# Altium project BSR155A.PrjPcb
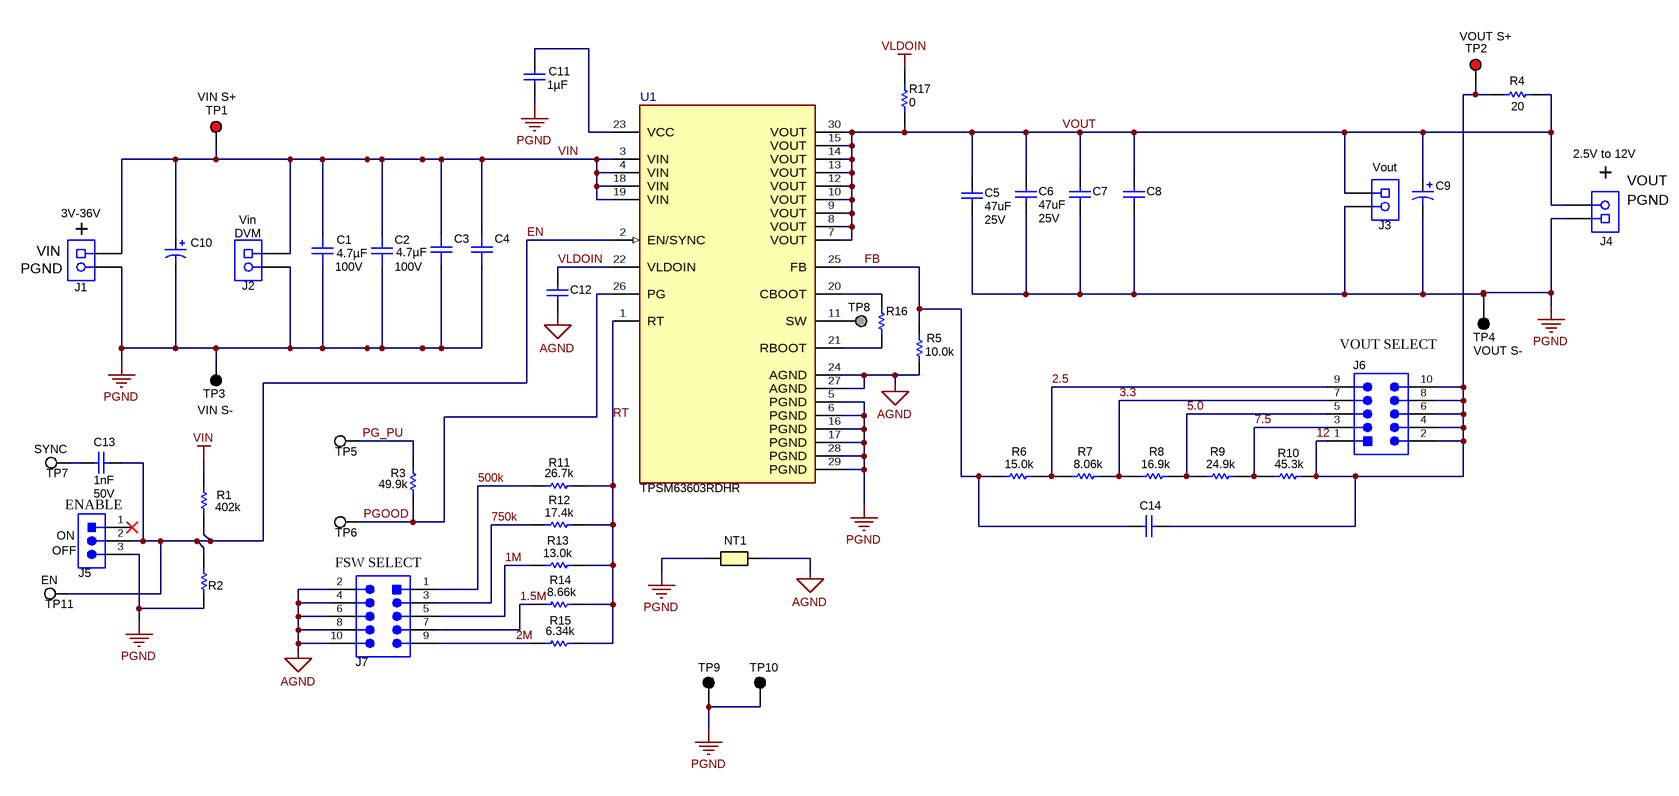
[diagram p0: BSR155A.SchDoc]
CopyrightYear: 2020; EVM_Orderable: TPSM63603EVM; PCB_Layout: Jason Arrigo; PCB_Rev: A; PRJ_Customer: Public Release; PRJ_Engineer: Jason Arrigo; PRJ_Number: BSR155; PRJ_Title: TPSM63603EVM; SCH_Rev: A; TechSupport: http://www.ti.com/support; TID: N/A
1 sheet, 51 parts. Net scope: global (net labels, ports and power ports of the same name join across sheets).
Board files: BSR155A.PcbDoc, BSR155A_ASCII.PcbDoc

## Sheet BSR155A.SchDoc: TPSM63603EVM schematic
size 431 x 279 mm; REV: E1; Date: Not shown in title block; ApprovedBy: Not shown in title block; CheckedBy: Not shown in title block; Author: Not shown in title block; CompanyName: Not shown in title block; DrawnBy: Jason Arrigo; Engineer: Not shown in title block; Organization: Not shown in title block; Address1: Not shown in title block; Address2: Not shown in title block; Address3: Not shown in title block; Address4: Not shown in title block; DocumentNumber: 1; Revision: Use project parameter SCH_Rev; SheetNumber: 1; SheetTotal: 2; PageSetup: Record=PageOptions¦CenterHorizontal=True¦CenterVertical=True¦PrintScale=1.00¦XCorrection=1.00¦YCorrection=1.00¦PrintKind=0¦BorderSize=5000000¦LeftOffset=0¦BottomOffset=0¦Orientation=2¦PaperLength=1000¦PaperWidth=1000¦Scale=100¦PaperSource=15¦PrintQuality=600¦MediaType=1¦DitherType=10¦PaperKind=Letter¦PrintScaleMode=1

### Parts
C1  value 4.7µF  VDC_V: 100V  [FP-GRM31CC72A475KE11L_1206-MFG]  (hidden comment: GRM31CC72A475KE11L)
C2  Cap_F: 4.7µF  VDC_V: 100V  [FP-GRM31CC72A475KE11L_1206-MFG]  (hidden comment: GRM31CC72A475KE11L)
C3  GRM31CC72A475KE11L  [FP-GRM31CC72A475KE11L_1206-MFG]  (value not drawn)
C4  GRM31CC72A475KE11L  [FP-GRM31CC72A475KE11L_1206-MFG]  (value not drawn)
C5  ValueDisplayed: 47uF  VDC_V: 25V  [1206_190L]  (hidden comment: C3216X5R1E476M160AC)
C6  ValueDisplayed: 47uF  VDC_V: 25V  [1206_190L]  (hidden comment: C3216X5R1E476M160AC)
C7  C3216X5R1E476M160AC  [1206_190L]  (value not drawn)
C8  C3216X5R1E476M160AC  [1206_190L]  (value not drawn)
C9  T520Y337M010ATE035  [7343-40]  (value not drawn)
C10  EEEFT1H470AP  [Panasonic_D]  (value not drawn)
C11  Cap_F: 1µF  [0402S]  (hidden comment: EMK105BJ105KVHF)
C12  GRM155R61E105KA12D  [0402S]  (value not drawn)
C13  Cap_F: 1nF  VDC_V: 50V  [0603]  (hidden comment: C0603C102J5RACTU)
C14  GRM188R71C472KA01D  [0603L]  (value not drawn)
J1  OSTTA024163  [On-Shore_OSTTA024163]  (value not drawn)
J2  310-43-102-41-001000  [Mill-max_310-43-102-41-001000]  (value not drawn)
J3  310-43-102-41-001000  [Mill-max_310-43-102-41-001000]  (value not drawn)
J4  OSTTA024163  [On-Shore_OSTTA024163]  (value not drawn)
J5  PEC03SAAN  [CONN_PEC03SAAN]  (value not drawn)
J6  PEC05DAAN  [CONN_PEC05DAAN]  (value not drawn)
J7  PEC05DAAN  [CONN_PEC05DAAN]  (value not drawn)
NT1  Net-Tie  [Net-Tie_10mil]  (value not drawn)  (net tie, no BOM)
R1  ValueDisplayed: 402k  [0603]  (hidden comment: CRCW0603402KFKEA)
R2  CRCW0603133KFKEA  [0603]  (value not drawn)
R3  ValueDisplayed: 49.9k  [0603]  (hidden comment: CRCW060349K9FKEA)
R4  ValueDisplayed: 20  [0603]  (hidden comment: CRCW060320R0JNEA)
R5  ValueDisplayed: 10.0k  [0603]  (hidden comment: CRCW060310K0FKEA)
R6  ValueDisplayed: 15.0k  [0603]  (hidden comment: CRCW060315K0FKEA)
R7  ValueDisplayed: 8.06k  [0603]  (hidden comment: CRCW06038K06FKEA)
R8  ValueDisplayed: 16.9k  [0603]  (hidden comment: CRCW060316K9FKEA)
R9  ValueDisplayed: 24.9k  [0603]  (hidden comment: CRCW060324K9FKEA)
R10  ValueDisplayed: 45.3k  [0603]  (hidden comment: CRCW060345K3FKEA)
R11  ValueDisplayed: 26.7k  [0603]  (hidden comment: CRCW060326K7FKEA)
R12  ValueDisplayed: 17.4k  [0603]  (hidden comment: CRCW060317K4FKEA)
R13  ValueDisplayed: 13.0k  [0603]  (hidden comment: CRCW060313K0FKEA)
R14  ValueDisplayed: 8.66k  [0603]  (hidden comment: CRCW06038K66FKEA)
R15  ValueDisplayed: 6.34k  [0603]  (hidden comment: CRCW06036K34FKEA)
R16  CRCW040210R0JNED  [0402S]  (value not drawn)
R17  ValueDisplayed: 0  [0603]  (hidden comment: RMCF0603ZT0R00)
TP1  5010  [Keystone5010]  (value not drawn)
TP2  5010  [Keystone5010]  (value not drawn)
TP3  5011  [Keystone5011]  (value not drawn)
TP4  5011  [Keystone5011]  (value not drawn)
TP5  5012  [Keystone5012]  (value not drawn)
TP6  5012  [Keystone5012]  (value not drawn)
TP7  5012  [Keystone5012]  (value not drawn)
TP8  TESTPOINT  [TP_25MIL-SMT]  (value not drawn)  (no BOM)
TP9  5011  [Keystone5011]  (value not drawn)
TP10  5011  [Keystone5011]  (value not drawn)
TP11  5012  [Keystone5012]  (value not drawn)
U1  TPSM63603RDHR  [RDH0030A-MFG]

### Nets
AGND: C12.2 J7.2 J7.4 J7.6 J7.8 J7.10 NT1.1 R5.1 U1.24(AGND) U1.27(AGND)
PGND: C1.1 C2.1 C3.1 C4.1 C5.1 C6.1 C7.1 C8.1 C9.2(-) C10.2(-) C11.2 J1.2 J2.2 J3.2 J4.1 J5.3 NT1.2 R2.1 TP3.1 TP4.1 TP9.1 TP10.1 U1.5(PGND) U1.6(PGND) U1.16(PGND) U1.17(PGND) U1.28(PGND) U1.29(PGND)
VIN: C1.2 C2.2 C3.2 C4.2 C10.1(+) J1.1 J2.1 R1.2 TP1.1 U1.3(VIN) U1.4(VIN) U1.18(VIN) U1.19(VIN)
VLDOIN: C12.1 R17.2 U1.22(VLDOIN)
1.5M: J7.7 R14.1
1M: J7.5 R13.1
2.5: J6.9 R6.2 R7.1
2M: J7.9 R15.1
3.3: J6.7 R7.2 R8.1
5.0: J6.5 R8.2 R9.1
7.5: J6.3 R9.2 R10.1
12: C14.2 J6.1 J6.2 J6.4 J6.6 J6.8 J6.10 R4.2 R10.2 TP2.1
500k: J7.1 R11.1
750k: J7.3 R12.1
EN: C13.2 J5.2 R1.1 R2.2 TP11.1 U1.2(EN/SYNC)
FB: C14.1 R5.2 R6.1 U1.25(FB)
PG_PU: R3.1 TP5.1
PGOOD: R3.2 TP6.1 U1.26(PG)
RT: R11.2 R12.2 R13.2 R14.2 R15.2 U1.1(RT)
VOUT: C5.2 C6.2 C7.2 C8.2 C9.1(+) J3.1 J4.2 R4.1 R17.1 U1.7(VOUT) U1.8(VOUT) U1.9(VOUT) U1.10(VOUT) U1.12(VOUT) U1.13(VOUT) U1.14(VOUT) U1.15(VOUT) U1.30(VOUT)
NetC11_1: C11.1 U1.23(VCC)
NetC13_1: C13.1 TP7.1
NetR16_1: R16.1 U1.21(RBOOT)
NetR16_2: R16.2 U1.20(CBOOT)
NetTP8_1: TP8.1 U1.11(SW)

Not connected (* = marked no-connect by the designer): J5 1*

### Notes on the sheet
- (near TP2) VOUT S+
- (near TP1) VIN S+
- (near J1) 3V-36V
- Vout
- (near J4) +
- 2.5V to 12V
- (near J4) PGND
- (near J4) VOUT
- (near J1) PGND
- (near J1) VIN
- (near J1) +
- (near J2) Vin
- (near J2) DVM
- (near TP3) VIN S-
- (near J6) VOUT SELECT
- (near TP4) VOUT S-
- (near TP7) SYNC
- (near J5) ENABLE
- ON
- (near TP11) EN
- OFF
- (near J7) FSW SELECT

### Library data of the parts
C1-C4 = CMP-0089881-1: 4.7µF ±10% 100V Ceramic Capacitor X7S 1206 (3216 Metric); Manufacturer: Murata; ValueDisplayed: 4.7uF; TempCo: 22%; SizeZ_mm: 1.9mm; AEC Qualified: No
C5 C6 = CMP-0008656-2: CAP, CERM, 47 uF, 25 V, +/- 20%, X5R, 1206_190; Manufacturer: TDK; Polarized: N; CompType: Capacitor; Value: 47uF; U/M: EA; Cap_F: 47µF; Value1: Unknown; TaMin_C: -55°C; TaMax_C: 85°C; Cap_Case: 1206; SizeArea_mm2: 5.12; SizeAreaWB_mm2: 10.92; SizeX_mm: 3.2; SizeY_mm: 1.6; SizeZ_mm: 1.9; AEC Category: Q200
C7 C8 = CMP-0008656-2: CAP, CERM, 47 uF, 25 V, +/- 20%, X5R, 1206_190; Manufacturer: TDK; Polarized: N; CompType: Capacitor; Value: 47uF; U/M: EA; Cap_F: 47µF; Value1: Unknown; VDC_V: 25V; TaMin_C: -55°C; TaMax_C: 85°C; Cap_Case: 1206; SizeArea_mm2: 5.12; SizeAreaWB_mm2: 10.92; SizeX_mm: 3.2; SizeY_mm: 1.6; SizeZ_mm: 1.9; AEC Category: Q200
C9 = CMP-0064986-2: CAP, Tantalum Polymer, 330 uF, 10 V,+/- 20%, 0.035 ohm, 7343-40 SMD; Manufacturer: Kemet; TaMin_C: -55°C; ESR_ohm: 0.035; Polarized: Y; SizeAreaWB_mm2: 58.59; Value: 330uF; TaMax_C: 105°C; SizeZ_mm: 4; SizeX_mm: 7.3; SizeY_mm: 4.3; Value2: 10V; SizeArea_mm2: 31.39; CompType: Capacitor; AEC Qualified: N; Cap_F: 330µF; AEC Category: Q200
C10 = CMP-0011204-2: CAP, AL, 47 uF, 50 V, +/- 20%, 0.68 ohm, AEC-Q200 Grade 2, SMD; Manufacturer: Panasonic; Polarized: Y; CompType: Capacitor; Value: 47uF; Cap_F: 47µF; VDC_V: 50V; ESR_ohm: 6.8d; IRMS_A: 1.95dA; TaMin_C: -55°C; TaMax_C: 105°C; Cap_Case: 6.3x5.8mm; SizeAreaWB_mm2: 73.96; SizeZ_mm: 6.1; SizeX_mm: 6.6; SizeArea_mm2: 43.56; AEC Grade: 2; AEC Category: Q200; U/M: EA
C11 = CMP-0006347-2: CAP, CERM, 1 uF, 16 V, +/- 10%, X5R, 0402; Manufacturer: Taiyo Yuden; Polarized: N; Value: 1uF; U/M: EA; Value1: Unknown; VDC_V: 16V; TaMin_C: -55°C; TaMax_C: 85°C; Cap_Case: 0402; SizeArea_mm2: 0.5; SizeAreaWB_mm2: 3; SizeX_mm: 1; SizeZ_mm: 0.6; AEC Category: Q200
C12 = CMP-0006608-2: CAP, CERM, 1 uF, 25 V, +/- 10%, X5R, 0402; Manufacturer: MuRata; Polarized: N; Value: 1uF; U/M: EA; Cap_F: 1µF; Value1: Unknown; VDC_V: 25V; TaMin_C: -55°C; TaMax_C: 85°C; Cap_Case: 0402; SizeArea_mm2: 0.5; SizeAreaWB_mm2: 3; SizeX_mm: 1; SizeZ_mm: 0.6; AEC Category: Q200
C13 = CMP-0006845-4: CAP, CERM, 1000 pF, 50 V, +/- 5%, X7R, 0603; Manufacturer: Kemet; Polarized: N; Value: 1000pF; U/M: EA; Value1: Unknown; TaMin_C: -55°C; TaMax_C: 125°C; SizeArea_mm2: 1.28; SizeAreaWB_mm2: 4.68; SizeX_mm: 1.6; SizeY_mm: 0.8; SizeZ_mm: 1; AEC Category: Q200
C14 = CMP-0007396-4: CAP, CERM, 4700 pF, 16 V, +/- 10%, X7R, 0603; Manufacturer: MuRata; Polarized: N; Value: 4700pF; U/M: EA; Cap_F: 4.7nF; Value1: Unknown; VDC_V: 16V; TaMin_C: -55°C; TaMax_C: 125°C; Cap_Case: 0603; SizeArea_mm2: 1.28; SizeAreaWB_mm2: 4.68; SizeX_mm: 1.6; SizeY_mm: 0.8; SizeZ_mm: 1; AEC Category: Q200
J1 = CMP-0074959-1: Terminal Block, 2x1, 5.08mm, TH; Manufacturer: On-Shore Technology; CNHeader: False; Green_Lifecycle: Not Set; Green_REACh: Incomplete; CT: True
J2 J3 = CMP-0055017-1: Socket Strip, 2x1, 100mil, Black, Tin, TH; Manufacturer: Mill-Max; CompType: Receptacle; Green_Lifecycle: Active; Green_REACh: Passed; CT: FALSE
J4 = CMP-0074959-1: Terminal Block, 2x1, 5.08mm, TH; Manufacturer: On-Shore Technology; CT: True; Green_REACh: Incomplete; CNHeader: False; Green_Lifecycle: Not Set
J5 = CMP-0002338-1: Header, 100mil, 3x1, Tin, TH; Manufacturer: Sullins Connector Solutions; Pitch_mm: 2.54; Gender: Male; Shrouded: N; Row_Count: 1; Current_A: 3A; Voltage_V: 1.8kV; Cert_UL: Y; Green_Lifecycle: Not Set; Green_REACh: Incomplete; CNHeader: TRUE; CT: FALSE
J6 J7 = CMP-0054550-2: Header, 100mil, 5x2, Tin, TH; Manufacturer: Sullins Connector Solutions; Pitch_mm: 2.54; Gender: Male; Cert_UL: Y; Voltage_V: 1.8kV; Green_REACh: Passed; Current_A: 3A; Shrouded: N; Green_Lifecycle: Active; Row_Count: 2
NT1 = CMP-0078142-3: Single point connection between nets.
R1 = CMP-0022408-4: RES, 402 k, 1%, 0.1 W, AEC-Q200 Grade 0, 0603; Manufacturer: Vishay-Dale; Power_W: 100mW; Value2: 0.1W; VDC_V: 75V; TempCo: 100 ppm/C; EIA_Code: E96; Value: 402k; SizeArea_mm2: 1.28; SizeX_mm: 1.6; SizeY_mm: 0.8; SizeZ_mm: 1; AEC Category: Q200; AEC Qualified: Y; AEC Grade: 0
R2 = CMP-0022038-4: RES, 133 k, 1%, 0.1 W, AEC-Q200 Grade 0, 0603; Manufacturer: Vishay-Dale; Res_ohm: 133k; Power_W: 100mW; Value2: 0.1W; VDC_V: 75V; TempCo: 100 ppm/C; EIA_Code: E96; Value: 133k; SizeArea_mm2: 1.28; SizeX_mm: 1.6; SizeY_mm: 0.8; SizeZ_mm: 1; AEC Category: Q200; AEC Qualified: Y; AEC Grade: 0
R3 = CMP-0022447-4: RES, 49.9 k, 1%, 0.1 W, AEC-Q200 Grade 0, 0603; Manufacturer: Vishay-Dale; CompType: Resistor; Value_Code: 49k9; Power_W: 100mW; Value2: 0.1W; VDC_V: 75V; TempCo: 100 ppm/C; EIA_Code: E96; Value: 49.9k; SizeArea_mm2: 1.28; SizeX_mm: 1.6; SizeY_mm: 0.8; SizeZ_mm: 1; AEC Category: Q200; AEC Qualified: Y; AEC Grade: 0
R4 = CMP-0025754-4: RES, 20, 5%, 0.1 W, AEC-Q200 Grade 0, 0603; Manufacturer: Vishay-Dale; Value: 20; Value_Code: 20R0; Power_W: 100mW; Value2: 0.1W; VDC_V: 75V; TempCo: 200 ppm/C; EIA_Code: E24; SizeArea_mm2: 1.28; SizeX_mm: 1.6; SizeY_mm: 0.8; SizeZ_mm: 1; AEC Category: Q200; AEC Qualified: Y; AEC Grade: 0
R5 = CMP-0021998-4: RES, 10.0 k, 1%, 0.1 W, AEC-Q200 Grade 0, 0603; Manufacturer: Vishay-Dale; Power_W: 100mW; TempCo: 100 ppm/C; Value_Code: 10k0; Value: 10.0k; EIA_Code: E96; Res_ohm: 10k; SizeX_mm: 1.6; SizeY_mm: 0.8; SizeZ_mm: 1; Value2: 0.1W; SizeArea_mm2: 1.28; AEC Qualified: Y; VDC_V: 75V; AEC Category: Q200; AEC Grade: 0
R6 = CMP-0022066-4: RES, 15.0 k, 1%, 0.1 W, AEC-Q200 Grade 0, 0603; Manufacturer: Vishay-Dale; Value: 15.0k; Res_ohm: 15k; Value_Code: 15k0; Power_W: 100mW; Value2: 0.1W; VDC_V: 75V; TempCo: 100 ppm/C; SizeArea_mm2: 1.28; SizeX_mm: 1.6; SizeY_mm: 0.8; SizeZ_mm: 1; EIA_Code: E96; AEC Category: Q200; AEC Qualified: Y; AEC Grade: 0
R7 = CMP-0022634-4: RES, 8.06 k, 1%, 0.1 W, AEC-Q200 Grade 0, 0603; Manufacturer: Vishay-Dale; Value: 8.06k; Value_Code: 8k06; Power_W: 100mW; Value2: 0.1W; VDC_V: 75V; TempCo: 100 ppm/C; SizeArea_mm2: 1.28; SizeX_mm: 1.6; SizeY_mm: 0.8; SizeZ_mm: 1; EIA_Code: E96; AEC Category: Q200; AEC Qualified: Y; AEC Grade: 0
R8 = CMP-0022081-4: RES, 16.9 k, 1%, 0.1 W, AEC-Q200 Grade 0, 0603; Manufacturer: Vishay-Dale; Value: 16.9k; Value_Code: 16k9; Power_W: 100mW; Value2: 0.1W; VDC_V: 75V; TempCo: 100 ppm/C; SizeArea_mm2: 1.28; SizeX_mm: 1.6; SizeY_mm: 0.8; SizeZ_mm: 1; EIA_Code: E96; AEC Category: Q200; AEC Qualified: Y; AEC Grade: 0
R9 = CMP-0022237-4: RES, 24.9 k, 1%, 0.1 W, AEC-Q200 Grade 0, 0603; Manufacturer: Vishay-Dale; Value: 24.9k; Value_Code: 24k9; Power_W: 100mW; Value2: 0.1W; VDC_V: 75V; TempCo: 100 ppm/C; SizeArea_mm2: 1.28; SizeX_mm: 1.6; SizeY_mm: 0.8; SizeZ_mm: 1; EIA_Code: E96; AEC Category: Q200; AEC Qualified: Y; AEC Grade: 0
R10 = CMP-0022430-4: RES, 45.3 k, 1%, 0.1 W, AEC-Q200 Grade 0, 0603; Manufacturer: Vishay-Dale; Value: 45.3k; Value_Code: 45k3; Power_W: 100mW; Value2: 0.1W; VDC_V: 75V; TempCo: 100 ppm/C; SizeArea_mm2: 1.28; SizeX_mm: 1.6; SizeY_mm: 0.8; SizeZ_mm: 1; EIA_Code: E96; AEC Category: Q200; AEC Qualified: Y; AEC Grade: 0
R11 = CMP-0022249-4: RES, 26.7 k, 1%, 0.1 W, AEC-Q200 Grade 0, 0603; Manufacturer: Vishay-Dale; Value: 26.7k; Value_Code: 26k7; Power_W: 100mW; Value2: 0.1W; VDC_V: 75V; TempCo: 100 ppm/C; SizeArea_mm2: 1.28; SizeX_mm: 1.6; SizeY_mm: 0.8; SizeZ_mm: 1; EIA_Code: E96; AEC Category: Q200; AEC Qualified: Y; AEC Grade: 0
R12 = CMP-0022089-4: RES, 17.4 k, 1%, 0.1 W, AEC-Q200 Grade 0, 0603; Manufacturer: Vishay-Dale; Value: 17.4k; Value_Code: 17k4; Power_W: 100mW; Value2: 0.1W; VDC_V: 75V; TempCo: 100 ppm/C; SizeArea_mm2: 1.28; SizeX_mm: 1.6; SizeY_mm: 0.8; SizeZ_mm: 1; EIA_Code: E96; AEC Category: Q200; AEC Qualified: Y; AEC Grade: 0
R13 = CMP-0022042-4: RES, 13.0 k, 1%, 0.1 W, AEC-Q200 Grade 0, 0603; Manufacturer: Vishay-Dale; Value: 13.0k; Res_ohm: 13k; Value_Code: 13k0; Power_W: 100mW; Value2: 0.1W; VDC_V: 75V; TempCo: 100 ppm/C; SizeArea_mm2: 1.28; SizeX_mm: 1.6; SizeY_mm: 0.8; SizeZ_mm: 1; EIA_Code: E96; AEC Category: Q200; AEC Qualified: Y; AEC Grade: 0
R14 = CMP-0022637-4: RES, 8.66 k, 1%, 0.1 W, AEC-Q200 Grade 0, 0603; Manufacturer: Vishay-Dale; Value: 8.66k; Value_Code: 8k66; Power_W: 100mW; Value2: 0.1W; VDC_V: 75V; TempCo: 100 ppm/C; SizeArea_mm2: 1.28; SizeX_mm: 1.6; SizeY_mm: 0.8; SizeZ_mm: 1; EIA_Code: E96; AEC Category: Q200; AEC Qualified: Y; AEC Grade: 0
R15 = CMP-0022560-4: RES, 6.34 k, 1%, 0.1 W, AEC-Q200 Grade 0, 0603; Manufacturer: Vishay-Dale; Value: 6.34k; Value_Code: 6k34; Power_W: 100mW; Value2: 0.1W; VDC_V: 75V; TempCo: 100 ppm/C; SizeArea_mm2: 1.28; SizeX_mm: 1.6; SizeY_mm: 0.8; SizeZ_mm: 1; EIA_Code: E96; AEC Category: Q200; AEC Qualified: Y; AEC Grade: 0
R16 = CMP-0026827-3: RES, 10, 5%, 0.063 W, AEC-Q200 Grade 0, 0402; Manufacturer: Vishay-Dale; Power_W: 63mW; TempCo: 200 ppm/C; Value_Code: 10R0; Value: 10; EIA_Code: E24; SizeX_mm: 1; SizeY_mm: 0.5; SizeZ_mm: 0.6; Value2: 0.063W; AEC Qualified: Y; VDC_V: 50V; AEC Category: Q200; AEC Grade: 0
R17 = CMP-0023343-3: RES, 0, 1%, 0.1 W, AEC-Q200 Grade 0, 0603; Manufacturer: Stackpole Electronics Inc; Power_W: 100mW; Value2: 0.1W; TempCo: ppm/C; Value: 0; SizeArea_mm2: 1.28; SizeX_mm: 1.6; SizeY_mm: 0.8; SizeZ_mm: 1; AEC Category: Q200; AEC Qualified: Y; U/M: EA
TP1 TP2 = CMP-0055147-1: Test Point, Multipurpose, Red, TH; Manufacturer: Keystone; CNHeader: FALSE; Green_Lifecycle: Active; Green_REACh: Passed; ContactFinish: Silver; CT: TRUE
TP3 = CMP-0055148-1: Test Point, Multipurpose, Black, TH; Manufacturer: Keystone; ContactFinish: Silver; CNHeader: FALSE; CT: TRUE; Green_Lifecycle: Active; Green_REACh: Passed
TP4 TP9 TP10 = CMP-0055148-1: Test Point, Multipurpose, Black, TH; Manufacturer: Keystone; CNHeader: FALSE; Green_Lifecycle: Active; Green_REACh: Passed; ContactFinish: Silver; CT: TRUE
TP5-TP7 TP11 = CMP-0055149-1: Test Point, Multipurpose, White, TH; Manufacturer: Keystone; CNHeader: FALSE; Green_Lifecycle: Active; Green_REACh: Passed; ContactFinish: Silver; CT: TRUE
TP8 = CMP-0078143-3: TEST POINT.  No entry in BOM.
U1 = CMP-0090663-2: TPSM63603 Cruzline Power Module; Manufacturer: Texas Instruments; SizeZ_mm: 1.9mm; TaMin_C: -40°C; TaMax_C: +105°C; Number Of Outputs: 1; Output Type: AdjustableProgrammable; TJmax_C: +125°C; Switching Topology: Buck; Switching Frequency: 200-2200kHz; CompType: IC; Min Supply Voltage: 3V; AEC Category: Q200; Nominal Supply Current: 9uA; Max Supply Voltage: 36V; Output Voltage: 1-12V; Standoff Height: 0mm

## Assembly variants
001: not fitted C3 C4 C7 C8 C9 C10 C12 C14 FID1 FID2 FID3 FID4 FID5 FID6 R2 R16 TP8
